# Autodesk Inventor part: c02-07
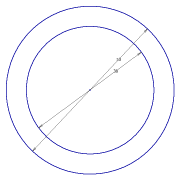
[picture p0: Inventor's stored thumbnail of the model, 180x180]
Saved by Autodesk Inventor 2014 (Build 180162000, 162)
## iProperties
Created: 2013-03
Part Number: c02-07
Material: Generic
Document SubType Name: Modeling
Designer: Thom Tremblay
Density: 1 g/cm^3
Appearance: Default
Author: Thom Tremblay
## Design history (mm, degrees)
sketch "Sketch1"
  geometry: C1 r 19 at (0, 0); C2 r 25 at (0, 0); 1 further point
  constraints: 2 centre point, 2 coincident
  dimensions: "d0" = 38 dimension on point (0, 0) C1.centre C1 C2.centre C2; "d0" = 38 diameter of C1; "d1" = 50 diameter of C2
